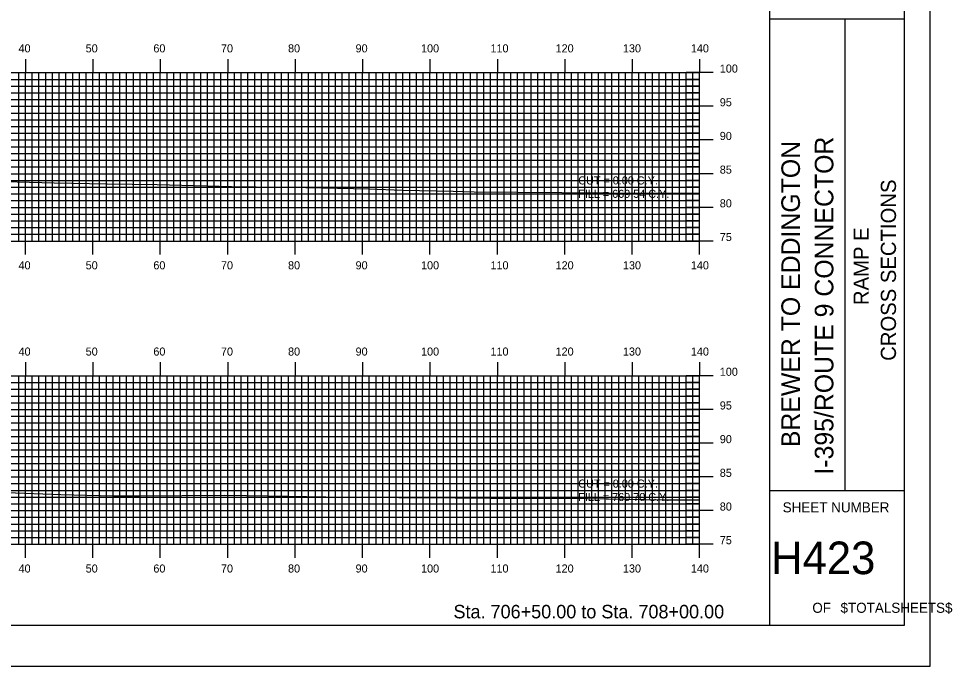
# Model space of a CAD drawing. Extents: x 854116 to 854460, y 364366 to 364586.
# Drawn here: x 854321.2 to 854459.7, y 364365.7 to 364461.8 of the extents above; entities that cross this region are included whole.
import ezdxf

# ---------------------------------------------------------------- set-up
doc = ezdxf.new("R2010")
doc.units = 0
for name, color, linetype in [('BORDER', 7, 'Continuous'), ('D_Text_Standard', 7, 'Continuous'), ('H_V ANNOTATION', 7, 'Continuous'), ('MAJOR', 7, 'Continuous'), ('MINOR', 7, 'Continuous'), ('PLOT BOUNDARY', 7, 'Continuous'), ('S_Roadway_Centerline', 7, 'Continuous')]:
    doc.layers.add(name, color=color, linetype=linetype)

msp = doc.modelspace()

# ---------------------------------------------------------------- linework, layer by layer
at = {"layer": 'BORDER'}
for p, q in [((854432.63, 364371.79), (854432.63, 364581.79)), ((854432.63, 364461.79), (854452.63, 364461.79)), ((854443.81, 364391.79), (854443.81, 364461.79)), ((854432.63, 364391.79), (854452.63, 364391.79))]:
    msp.add_line(p, q, dxfattribs=at)
msp.add_lwpolyline([(854132.63, 364371.79), (854452.63, 364371.79), (854452.63, 364581.79), (854132.63, 364581.79)], close=True, dxfattribs=at)
at = {"layer": 'MAJOR'}
for p, q in [((854322.23, 364455.79), (854322.23, 364453.79)), ((854332.23, 364455.79), (854332.23, 364453.79)), ((854342.23, 364455.79), (854342.23, 364453.79)), ((854352.23, 364455.79), (854352.23, 364453.79)), ((854362.23, 364455.79), (854362.23, 364453.79)), ((854372.23, 364455.79), (854372.23, 364453.79)), ((854382.23, 364455.79), (854382.23, 364453.79)), ((854392.23, 364455.79), (854392.23, 364453.79)), ((854402.23, 364455.79), (854402.23, 364453.79)), ((854412.23, 364455.79), (854412.23, 364453.79)), ((854422.23, 364455.79), (854422.23, 364453.79)), ((854142.23, 364453.79), (854422.23, 364453.79)), ((854142.23, 364453.79), (854422.23, 364453.79)), ((854322.23, 364428.79), (854322.23, 364453.79)), ((854332.23, 364428.79), (854332.23, 364453.79)), ((854342.23, 364428.79), (854342.23, 364453.79)), ((854352.23, 364428.79), (854352.23, 364453.79)), ((854362.23, 364428.79), (854362.23, 364453.79)), ((854372.23, 364428.79), (854372.23, 364453.79)), ((854382.23, 364428.79), (854382.23, 364453.79)), ((854392.23, 364428.79), (854392.23, 364453.79)), ((854402.23, 364428.79), (854402.23, 364453.79)), ((854412.23, 364428.79), (854412.23, 364453.79)), ((854424.23, 364453.79), (854420.23, 364453.79)), ((854422.23, 364428.79), (854422.23, 364453.79)), ((854422.23, 364428.79), (854422.23, 364453.79)), ((854142.23, 364448.79), (854422.23, 364448.79)), ((854424.23, 364448.79), (854420.23, 364448.79)), ((854142.23, 364443.79), (854422.23, 364443.79)), ((854424.23, 364443.79), (854420.23, 364443.79)), ((854142.23, 364438.79), (854422.23, 364438.79)), ((854424.23, 364438.79), (854420.23, 364438.79)), ((854142.23, 364433.79), (854422.23, 364433.79)), ((854424.23, 364433.79), (854420.23, 364433.79)), ((854142.23, 364428.79), (854422.23, 364428.79)), ((854142.23, 364428.79), (854422.23, 364428.79)), ((854322.23, 364426.78), (854322.23, 364428.79)), ((854332.23, 364426.78), (854332.23, 364428.79)), ((854342.23, 364426.78), (854342.23, 364428.79)), ((854352.23, 364426.78), (854352.23, 364428.79)), ((854362.23, 364426.78), (854362.23, 364428.79)), ((854372.23, 364426.78), (854372.23, 364428.79)), ((854382.23, 364426.78), (854382.23, 364428.79)), ((854392.23, 364426.78), (854392.23, 364428.79)), ((854402.23, 364426.78), (854402.23, 364428.79)), ((854412.23, 364426.78), (854412.23, 364428.79)), ((854424.23, 364428.79), (854420.23, 364428.79)), ((854422.23, 364426.78), (854422.23, 364428.79)), ((854322.23, 364410.79), (854322.23, 364408.79)), ((854332.23, 364410.79), (854332.23, 364408.79)), ((854342.23, 364410.79), (854342.23, 364408.79)), ((854352.23, 364410.79), (854352.23, 364408.79)), ((854362.23, 364410.79), (854362.23, 364408.79)), ((854372.23, 364410.79), (854372.23, 364408.79)), ((854382.23, 364410.79), (854382.23, 364408.79)), ((854392.23, 364410.79), (854392.23, 364408.79)), ((854402.23, 364410.79), (854402.23, 364408.79)), ((854412.23, 364410.79), (854412.23, 364408.79)), ((854422.23, 364410.79), (854422.23, 364408.79)), ((854142.23, 364408.79), (854422.23, 364408.79)), ((854142.23, 364408.79), (854422.23, 364408.79)), ((854322.23, 364383.79), (854322.23, 364408.79)), ((854332.23, 364383.79), (854332.23, 364408.79)), ((854342.23, 364383.79), (854342.23, 364408.79)), ((854352.23, 364383.79), (854352.23, 364408.79)), ((854362.23, 364383.79), (854362.23, 364408.79)), ((854372.23, 364383.79), (854372.23, 364408.79)), ((854382.23, 364383.79), (854382.23, 364408.79)), ((854392.23, 364383.79), (854392.23, 364408.79)), ((854402.23, 364383.79), (854402.23, 364408.79)), ((854412.23, 364383.79), (854412.23, 364408.79)), ((854424.23, 364408.79), (854420.23, 364408.79)), ((854422.23, 364383.79), (854422.23, 364408.79)), ((854422.23, 364383.79), (854422.23, 364408.79)), ((854142.23, 364403.79), (854422.23, 364403.79)), ((854424.23, 364403.79), (854420.23, 364403.79)), ((854142.23, 364398.79), (854422.23, 364398.79)), ((854424.23, 364398.79), (854420.23, 364398.79)), ((854142.23, 364393.79), (854422.23, 364393.79)), ((854424.23, 364393.79), (854420.23, 364393.79)), ((854142.23, 364388.79), (854422.23, 364388.79)), ((854424.23, 364388.79), (854420.23, 364388.79)), ((854142.23, 364383.79), (854422.23, 364383.79)), ((854142.23, 364383.79), (854422.23, 364383.79)), ((854322.23, 364381.78), (854322.23, 364383.79)), ((854332.23, 364381.78), (854332.23, 364383.79)), ((854342.23, 364381.78), (854342.23, 364383.79)), ((854352.23, 364381.78), (854352.23, 364383.79)), ((854362.23, 364381.78), (854362.23, 364383.79)), ((854372.23, 364381.78), (854372.23, 364383.79)), ((854382.23, 364381.78), (854382.23, 364383.79)), ((854392.23, 364381.78), (854392.23, 364383.79)), ((854402.23, 364381.78), (854402.23, 364383.79)), ((854412.23, 364381.78), (854412.23, 364383.79)), ((854424.23, 364383.79), (854420.23, 364383.79)), ((854422.23, 364381.78), (854422.23, 364383.79))]:
    msp.add_line(p, q, dxfattribs=at)
at = {"layer": 'MINOR'}
for p, q in [((854142.23, 364452.79), (854422.23, 364452.79)), ((854321.23, 364428.79), (854321.23, 364453.79)), ((854323.23, 364428.79), (854323.23, 364453.79)), ((854324.23, 364428.79), (854324.23, 364453.79)), ((854325.23, 364428.79), (854325.23, 364453.79)), ((854326.23, 364428.79), (854326.23, 364453.79)), ((854327.23, 364428.79), (854327.23, 364453.79)), ((854328.23, 364428.79), (854328.23, 364453.79)), ((854329.23, 364428.79), (854329.23, 364453.79)), ((854330.23, 364428.79), (854330.23, 364453.79)), ((854331.23, 364428.79), (854331.23, 364453.79)), ((854333.23, 364428.79), (854333.23, 364453.79)), ((854334.23, 364428.79), (854334.23, 364453.79)), ((854335.23, 364428.79), (854335.23, 364453.79)), ((854336.23, 364428.79), (854336.23, 364453.79)), ((854337.23, 364428.79), (854337.23, 364453.79)), ((854338.23, 364428.79), (854338.23, 364453.79)), ((854339.23, 364428.79), (854339.23, 364453.79)), ((854340.23, 364428.79), (854340.23, 364453.79)), ((854341.23, 364428.79), (854341.23, 364453.79)), ((854343.23, 364428.79), (854343.23, 364453.79)), ((854344.23, 364428.79), (854344.23, 364453.79)), ((854345.23, 364428.79), (854345.23, 364453.79)), ((854346.23, 364428.79), (854346.23, 364453.79)), ((854347.23, 364428.79), (854347.23, 364453.79)), ((854348.23, 364428.79), (854348.23, 364453.79)), ((854349.23, 364428.79), (854349.23, 364453.79)), ((854350.23, 364428.79), (854350.23, 364453.79)), ((854351.23, 364428.79), (854351.23, 364453.79)), ((854353.23, 364428.79), (854353.23, 364453.79)), ((854354.23, 364428.79), (854354.23, 364453.79)), ((854355.23, 364428.79), (854355.23, 364453.79)), ((854356.23, 364428.79), (854356.23, 364453.79)), ((854357.23, 364428.79), (854357.23, 364453.79)), ((854358.23, 364428.79), (854358.23, 364453.79)), ((854359.23, 364428.79), (854359.23, 364453.79)), ((854360.23, 364428.79), (854360.23, 364453.79)), ((854361.23, 364428.79), (854361.23, 364453.79)), ((854363.23, 364428.79), (854363.23, 364453.79)), ((854364.23, 364428.79), (854364.23, 364453.79)), ((854365.23, 364428.79), (854365.23, 364453.79)), ((854366.23, 364428.79), (854366.23, 364453.79)), ((854367.23, 364428.79), (854367.23, 364453.79)), ((854368.23, 364428.79), (854368.23, 364453.79)), ((854369.23, 364428.79), (854369.23, 364453.79)), ((854370.23, 364428.79), (854370.23, 364453.79)), ((854371.23, 364428.79), (854371.23, 364453.79)), ((854373.23, 364428.79), (854373.23, 364453.79)), ((854374.23, 364428.79), (854374.23, 364453.79)), ((854375.23, 364428.79), (854375.23, 364453.79)), ((854376.23, 364428.79), (854376.23, 364453.79)), ((854377.23, 364428.79), (854377.23, 364453.79)), ((854378.23, 364428.79), (854378.23, 364453.79)), ((854379.23, 364428.79), (854379.23, 364453.79)), ((854380.23, 364428.79), (854380.23, 364453.79)), ((854381.23, 364428.79), (854381.23, 364453.79)), ((854383.23, 364428.79), (854383.23, 364453.79)), ((854384.23, 364428.79), (854384.23, 364453.79)), ((854385.23, 364428.79), (854385.23, 364453.79)), ((854386.23, 364428.79), (854386.23, 364453.79)), ((854387.23, 364428.79), (854387.23, 364453.79)), ((854388.23, 364428.79), (854388.23, 364453.79)), ((854389.23, 364428.79), (854389.23, 364453.79)), ((854390.23, 364428.79), (854390.23, 364453.79)), ((854391.23, 364428.79), (854391.23, 364453.79)), ((854393.23, 364428.79), (854393.23, 364453.79)), ((854394.23, 364428.79), (854394.23, 364453.79)), ((854395.23, 364428.79), (854395.23, 364453.79)), ((854396.23, 364428.79), (854396.23, 364453.79)), ((854397.23, 364428.79), (854397.23, 364453.79)), ((854398.23, 364428.79), (854398.23, 364453.79)), ((854399.23, 364428.79), (854399.23, 364453.79)), ((854400.23, 364428.79), (854400.23, 364453.79)), ((854401.23, 364428.79), (854401.23, 364453.79)), ((854403.23, 364428.79), (854403.23, 364453.79)), ((854404.23, 364428.79), (854404.23, 364453.79)), ((854405.23, 364428.79), (854405.23, 364453.79)), ((854406.23, 364428.79), (854406.23, 364453.79)), ((854407.23, 364428.79), (854407.23, 364453.79)), ((854408.23, 364428.79), (854408.23, 364453.79)), ((854409.23, 364428.79), (854409.23, 364453.79)), ((854410.23, 364428.79), (854410.23, 364453.79)), ((854411.23, 364428.79), (854411.23, 364453.79)), ((854413.23, 364428.79), (854413.23, 364453.79)), ((854414.23, 364428.79), (854414.23, 364453.79)), ((854415.23, 364428.79), (854415.23, 364453.79)), ((854416.23, 364428.79), (854416.23, 364453.79)), ((854417.23, 364428.79), (854417.23, 364453.79)), ((854418.23, 364428.79), (854418.23, 364453.79)), ((854419.23, 364428.79), (854419.23, 364453.79)), ((854420.23, 364428.79), (854420.23, 364453.79)), ((854422.23, 364452.79), (854420.23, 364452.79)), ((854421.23, 364428.79), (854421.23, 364453.79)), ((854142.23, 364451.79), (854422.23, 364451.79)), ((854422.23, 364451.79), (854420.23, 364451.79)), ((854142.23, 364450.79), (854422.23, 364450.79)), ((854422.23, 364450.79), (854420.23, 364450.79)), ((854142.23, 364449.79), (854422.23, 364449.79)), ((854422.23, 364449.79), (854420.23, 364449.79)), ((854142.23, 364447.79), (854422.23, 364447.79)), ((854422.23, 364447.79), (854420.23, 364447.79)), ((854142.23, 364446.79), (854422.23, 364446.79)), ((854142.23, 364445.79), (854422.23, 364445.79)), ((854422.23, 364446.79), (854420.23, 364446.79)), ((854422.23, 364445.79), (854420.23, 364445.79)), ((854142.23, 364444.79), (854422.23, 364444.79)), ((854422.23, 364444.79), (854420.23, 364444.79)), ((854142.23, 364442.79), (854422.23, 364442.79)), ((854142.23, 364441.79), (854422.23, 364441.79)), ((854422.23, 364442.79), (854420.23, 364442.79)), ((854422.23, 364441.79), (854420.23, 364441.79)), ((854142.23, 364440.79), (854422.23, 364440.79)), ((854422.23, 364440.79), (854420.23, 364440.79)), ((854142.23, 364439.79), (854422.23, 364439.79)), ((854422.23, 364439.79), (854420.23, 364439.79)), ((854142.23, 364437.79), (854422.23, 364437.79)), ((854422.23, 364437.79), (854420.23, 364437.79)), ((854142.23, 364436.79), (854422.23, 364436.79)), ((854422.23, 364436.79), (854420.23, 364436.79)), ((854142.23, 364435.79), (854422.23, 364435.79)), ((854142.23, 364434.79), (854422.23, 364434.79)), ((854422.23, 364435.79), (854420.23, 364435.79)), ((854422.23, 364434.79), (854420.23, 364434.79)), ((854142.23, 364432.79), (854422.23, 364432.79)), ((854422.23, 364432.79), (854420.23, 364432.79)), ((854142.23, 364431.79), (854422.23, 364431.79)), ((854142.23, 364430.79), (854422.23, 364430.79)), ((854422.23, 364431.79), (854420.23, 364431.79)), ((854422.23, 364430.79), (854420.23, 364430.79)), ((854142.23, 364429.79), (854422.23, 364429.79)), ((854422.23, 364429.79), (854420.23, 364429.79)), ((854321.23, 364383.79), (854321.23, 364408.79)), ((854323.23, 364383.79), (854323.23, 364408.79)), ((854324.23, 364383.79), (854324.23, 364408.79)), ((854325.23, 364383.79), (854325.23, 364408.79)), ((854326.23, 364383.79), (854326.23, 364408.79)), ((854327.23, 364383.79), (854327.23, 364408.79)), ((854328.23, 364383.79), (854328.23, 364408.79)), ((854329.23, 364383.79), (854329.23, 364408.79)), ((854330.23, 364383.79), (854330.23, 364408.79)), ((854331.23, 364383.79), (854331.23, 364408.79)), ((854333.23, 364383.79), (854333.23, 364408.79)), ((854334.23, 364383.79), (854334.23, 364408.79)), ((854335.23, 364383.79), (854335.23, 364408.79)), ((854336.23, 364383.79), (854336.23, 364408.79)), ((854337.23, 364383.79), (854337.23, 364408.79)), ((854338.23, 364383.79), (854338.23, 364408.79)), ((854339.23, 364383.79), (854339.23, 364408.79)), ((854340.23, 364383.79), (854340.23, 364408.79)), ((854341.23, 364383.79), (854341.23, 364408.79)), ((854343.23, 364383.79), (854343.23, 364408.79)), ((854344.23, 364383.79), (854344.23, 364408.79)), ((854345.23, 364383.79), (854345.23, 364408.79)), ((854346.23, 364383.79), (854346.23, 364408.79)), ((854347.23, 364383.79), (854347.23, 364408.79)), ((854348.23, 364383.79), (854348.23, 364408.79)), ((854349.23, 364383.79), (854349.23, 364408.79)), ((854350.23, 364383.79), (854350.23, 364408.79)), ((854351.23, 364383.79), (854351.23, 364408.79)), ((854353.23, 364383.79), (854353.23, 364408.79)), ((854354.23, 364383.79), (854354.23, 364408.79)), ((854355.23, 364383.79), (854355.23, 364408.79)), ((854356.23, 364383.79), (854356.23, 364408.79)), ((854357.23, 364383.79), (854357.23, 364408.79)), ((854358.23, 364383.79), (854358.23, 364408.79)), ((854359.23, 364383.79), (854359.23, 364408.79)), ((854360.23, 364383.79), (854360.23, 364408.79)), ((854361.23, 364383.79), (854361.23, 364408.79)), ((854363.23, 364383.79), (854363.23, 364408.79)), ((854364.23, 364383.79), (854364.23, 364408.79)), ((854365.23, 364383.79), (854365.23, 364408.79)), ((854366.23, 364383.79), (854366.23, 364408.79)), ((854367.23, 364383.79), (854367.23, 364408.79)), ((854368.23, 364383.79), (854368.23, 364408.79)), ((854369.23, 364383.79), (854369.23, 364408.79)), ((854370.23, 364383.79), (854370.23, 364408.79)), ((854371.23, 364383.79), (854371.23, 364408.79)), ((854373.23, 364383.79), (854373.23, 364408.79)), ((854374.23, 364383.79), (854374.23, 364408.79)), ((854375.23, 364383.79), (854375.23, 364408.79)), ((854376.23, 364383.79), (854376.23, 364408.79)), ((854377.23, 364383.79), (854377.23, 364408.79)), ((854378.23, 364383.79), (854378.23, 364408.79)), ((854379.23, 364383.79), (854379.23, 364408.79)), ((854380.23, 364383.79), (854380.23, 364408.79)), ((854381.23, 364383.79), (854381.23, 364408.79)), ((854383.23, 364383.79), (854383.23, 364408.79)), ((854384.23, 364383.79), (854384.23, 364408.79)), ((854385.23, 364383.79), (854385.23, 364408.79)), ((854386.23, 364383.79), (854386.23, 364408.79)), ((854387.23, 364383.79), (854387.23, 364408.79)), ((854388.23, 364383.79), (854388.23, 364408.79)), ((854389.23, 364383.79), (854389.23, 364408.79)), ((854390.23, 364383.79), (854390.23, 364408.79)), ((854391.23, 364383.79), (854391.23, 364408.79)), ((854393.23, 364383.79), (854393.23, 364408.79)), ((854394.23, 364383.79), (854394.23, 364408.79)), ((854395.23, 364383.79), (854395.23, 364408.79)), ((854396.23, 364383.79), (854396.23, 364408.79)), ((854397.23, 364383.79), (854397.23, 364408.79)), ((854398.23, 364383.79), (854398.23, 364408.79)), ((854399.23, 364383.79), (854399.23, 364408.79)), ((854400.23, 364383.79), (854400.23, 364408.79)), ((854401.23, 364383.79), (854401.23, 364408.79)), ((854403.23, 364383.79), (854403.23, 364408.79)), ((854404.23, 364383.79), (854404.23, 364408.79)), ((854405.23, 364383.79), (854405.23, 364408.79)), ((854406.23, 364383.79), (854406.23, 364408.79)), ((854407.23, 364383.79), (854407.23, 364408.79)), ((854408.23, 364383.79), (854408.23, 364408.79)), ((854409.23, 364383.79), (854409.23, 364408.79)), ((854410.23, 364383.79), (854410.23, 364408.79)), ((854411.23, 364383.79), (854411.23, 364408.79)), ((854413.23, 364383.79), (854413.23, 364408.79)), ((854414.23, 364383.79), (854414.23, 364408.79)), ((854415.23, 364383.79), (854415.23, 364408.79)), ((854416.23, 364383.79), (854416.23, 364408.79)), ((854417.23, 364383.79), (854417.23, 364408.79)), ((854418.23, 364383.79), (854418.23, 364408.79)), ((854419.23, 364383.79), (854419.23, 364408.79)), ((854420.23, 364383.79), (854420.23, 364408.79)), ((854421.23, 364383.79), (854421.23, 364408.79)), ((854142.23, 364407.79), (854422.23, 364407.79)), ((854422.23, 364407.79), (854420.23, 364407.79)), ((854142.23, 364406.79), (854422.23, 364406.79)), ((854142.23, 364405.79), (854422.23, 364405.79)), ((854422.23, 364406.79), (854420.23, 364406.79)), ((854422.23, 364405.79), (854420.23, 364405.79)), ((854142.23, 364404.79), (854422.23, 364404.79)), ((854422.23, 364404.79), (854420.23, 364404.79)), ((854142.23, 364402.79), (854422.23, 364402.79)), ((854142.23, 364401.79), (854422.23, 364401.79)), ((854422.23, 364402.79), (854420.23, 364402.79)), ((854422.23, 364401.79), (854420.23, 364401.79)), ((854142.23, 364400.79), (854422.23, 364400.79)), ((854422.23, 364400.79), (854420.23, 364400.79)), ((854142.23, 364399.79), (854422.23, 364399.79)), ((854422.23, 364399.79), (854420.23, 364399.79)), ((854142.23, 364397.79), (854422.23, 364397.79)), ((854422.23, 364397.79), (854420.23, 364397.79)), ((854142.23, 364396.79), (854422.23, 364396.79)), ((854422.23, 364396.79), (854420.23, 364396.79)), ((854142.23, 364395.79), (854422.23, 364395.79)), ((854142.23, 364394.79), (854422.23, 364394.79)), ((854422.23, 364395.79), (854420.23, 364395.79)), ((854422.23, 364394.79), (854420.23, 364394.79)), ((854142.23, 364392.79), (854422.23, 364392.79)), ((854142.23, 364391.79), (854422.23, 364391.79)), ((854422.23, 364392.79), (854420.23, 364392.79)), ((854422.23, 364391.79), (854420.23, 364391.79)), ((854142.23, 364390.79), (854422.23, 364390.79)), ((854422.23, 364390.79), (854420.23, 364390.79)), ((854142.23, 364389.79), (854422.23, 364389.79)), ((854422.23, 364389.79), (854420.23, 364389.79)), ((854142.23, 364387.79), (854422.23, 364387.79)), ((854422.23, 364387.79), (854420.23, 364387.79)), ((854142.23, 364386.79), (854422.23, 364386.79)), ((854422.23, 364386.79), (854420.23, 364386.79)), ((854142.23, 364385.79), (854422.23, 364385.79)), ((854422.23, 364385.79), (854420.23, 364385.79)), ((854142.23, 364384.79), (854422.23, 364384.79)), ((854422.23, 364384.79), (854420.23, 364384.79))]:
    msp.add_line(p, q, dxfattribs=at)
at = {"layer": 'PLOT BOUNDARY'}
msp.add_lwpolyline([(854116.44, 364365.67), (854456.44, 364365.67), (854456.44, 364585.67), (854116.44, 364585.67)], close=True, dxfattribs=at)
at = {"layer": 'S_Roadway_Centerline'}
for points in [[(854315.45, 364437.71), (854326.49, 364437.44), (854334.34, 364437.3), (854341.76, 364437.16), (854352.79, 364436.91), (854363.8, 364436.73), (854370.89, 364436.57), (854373.1, 364436.52), (854378.22, 364436.36), (854385.67, 364436.17), (854388.8, 364436.09), (854401.81, 364435.99), (854408.34, 364435.93), (854409.73, 364435.91), (854412.65, 364435.92), (854422.23, 364435.89)], [(854319.39, 364391.47), (854327.49, 364391.18), (854335.22, 364390.96), (854339.1, 364390.97), (854351.8, 364391.09), (854358.24, 364390.96), (854369.64, 364390.77), (854377.61, 364390.72), (854385.95, 364390.68), (854396.6, 364390.58), (854402.85, 364390.62), (854416.69, 364390.4), (854420.96, 364390.36), (854422.23, 364390.37)]]:
    msp.add_lwpolyline(points, dxfattribs=at)

# ---------------------------------------------------------------- texts
at = {"layer": 'BORDER'}
for s, height, p in [('BREWER TO EDDINGTON', 2.7557, (854437.12, 364398.2)), ('I-395/ROUTE 9 CONNECTOR', 2.7557, (854442.08, 364394.12)), ('CROSS SECTIONS', 2.25, (854451.37, 364411.01)), ('RAMP E', 2.25, (854447.32, 364419.29))]:
    msp.add_text(s, height=height, rotation=90, dxfattribs=at).set_placement(p)
for s, height, p in [('SHEET NUMBER', 1.4905, (854434.56, 364388.52)), ('H423', 4.839, (854432.84, 364379.35)), ('OF', 1.491, (854438.96, 364373.61)), ('$TOTALSHEETS$', 1.4905, (854443.14, 364373.61))]:
    msp.add_text(s, height=height, dxfattribs=at).set_placement(p)
at = {"layer": 'D_Text_Standard'}
for s, p in [('CUT = 0.00 C.Y.', (854404.23, 364437.19)), ('FILL = 669.54 C.Y.', (854404.23, 364435.2)), ('CUT = 0.00 C.Y.', (854404.23, 364392.19)), ('FILL = 769.70 C.Y.', (854404.23, 364390.2))]:
    msp.add_text(s, height=1.2, dxfattribs=at).set_placement(p)
at = {"layer": 'H_V ANNOTATION'}
for s, height, p in [('40', 1.2, (854321.2, 364456.79)), ('50', 1.2, (854331.16, 364456.79)), ('60', 1.2, (854341.2, 364456.79)), ('70', 1.2, (854351.23, 364456.79)), ('80', 1.2, (854361.18, 364456.79)), ('90', 1.2, (854371.2, 364456.79)), ('100', 1.2, (854380.91, 364456.79)), ('110', 1.2, (854391.21, 364456.79)), ('120', 1.2, (854400.87, 364456.79)), ('130', 1.2, (854410.86, 364456.79)), ('140', 1.2, (854420.94, 364456.79)), ('100', 1.2, (854425.23, 364453.79)), ('95', 1.2, (854425.23, 364448.79)), ('90', 1.2, (854425.23, 364443.79)), ('85', 1.2, (854425.23, 364438.79)), ('80', 1.2, (854425.23, 364433.79)), ('75', 1.2, (854425.23, 364428.79)), ('40', 1.2, (854321.2, 364424.59)), ('50', 1.2, (854331.16, 364424.59)), ('60', 1.2, (854341.2, 364424.59)), ('70', 1.2, (854351.23, 364424.59)), ('80', 1.2, (854361.18, 364424.59)), ('90', 1.2, (854371.2, 364424.59)), ('100', 1.2, (854380.91, 364424.59)), ('110', 1.2, (854391.21, 364424.59)), ('120', 1.2, (854400.87, 364424.59)), ('130', 1.2, (854410.86, 364424.59)), ('140', 1.2, (854420.94, 364424.59)), ('40', 1.2, (854321.2, 364411.79)), ('50', 1.2, (854331.16, 364411.79)), ('60', 1.2, (854341.2, 364411.79)), ('70', 1.2, (854351.23, 364411.79)), ('80', 1.2, (854361.18, 364411.79)), ('90', 1.2, (854371.2, 364411.79)), ('100', 1.2, (854380.91, 364411.79)), ('110', 1.2, (854391.21, 364411.79)), ('120', 1.2, (854400.87, 364411.79)), ('130', 1.2, (854410.86, 364411.79)), ('140', 1.2, (854420.94, 364411.79)), ('100', 1.2, (854425.23, 364408.79)), ('95', 1.2, (854425.23, 364403.79)), ('90', 1.2, (854425.23, 364398.79)), ('85', 1.2, (854425.23, 364393.79)), ('80', 1.2, (854425.23, 364388.79)), ('75', 1.2, (854425.23, 364383.79)), ('40', 1.2, (854321.2, 364379.59)), ('50', 1.2, (854331.16, 364379.59)), ('60', 1.2, (854341.2, 364379.59)), ('70', 1.2, (854351.23, 364379.59)), ('80', 1.2, (854361.18, 364379.59)), ('90', 1.2, (854371.2, 364379.59)), ('100', 1.2, (854380.91, 364379.59)), ('110', 1.2, (854391.21, 364379.59)), ('120', 1.2, (854400.87, 364379.59)), ('130', 1.2, (854410.86, 364379.59)), ('140', 1.2, (854420.94, 364379.59)), ('Sta. 706+50.00 to Sta. 708+00.00', 2.0004, (854385.72, 364372.79))]:
    msp.add_text(s, height=height, dxfattribs=at).set_placement(p)

doc.saveas('drawing.dxf')
